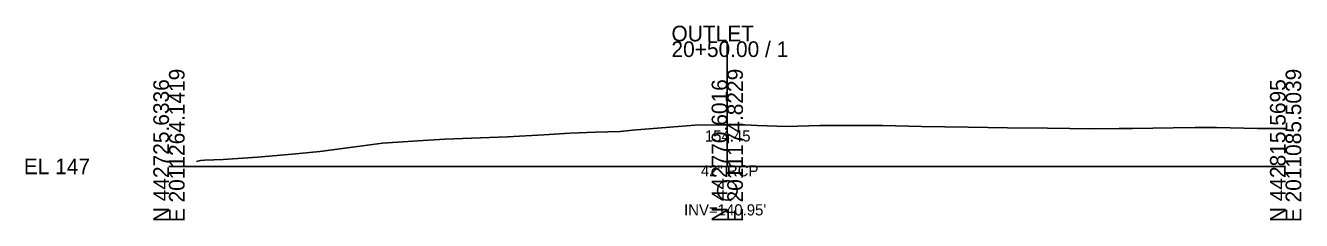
# Model space of a CAD drawing. Extents: x -26 to 1203, y -15 to 9526.
# Drawn here: x 974.3 to 1202.8, y 490.3 to 525.2 of the extents above; entities that cross this region are included whole.
import ezdxf

# ---------------------------------------------------------------- set-up
doc = ezdxf.new("R2010")
doc.units = 0
for name, color, linetype in [('Exist Cross Section Cell', 7, 'Continuous'), ('Exist XS Center Line Elevation Label', 7, 'Continuous'), ('Exist XS Ground Line', 7, 'Continuous'), ('Prop XSC Text', 7, 'Continuous')]:
    doc.layers.add(name, color=color, linetype=linetype)

msp = doc.modelspace()

# ---------------------------------------------------------------- linework, layer by layer
at = {"layer": 'Exist Cross Section Cell'}
for p, q in [((1100, 500), (1100, 522.39)), ((1000, 500), (1100, 500)), ((1100, 500), (1200, 500))]:
    msp.add_line(p, q, dxfattribs=at)
at = {"layer": 'Exist XS Ground Line'}
msp.add_lwpolyline([(1004.94, 500.9), (1005.66, 501.03), (1006.34, 501.11), (1009.71, 501.23), (1015.83, 501.65), (1022.04, 502.18), (1027.03, 502.69), (1031.95, 503.29), (1038.22, 504.15), (1044.59, 504.56), (1049.42, 504.88), (1054.19, 505.05), (1060.62, 505.26), (1067.14, 505.64), (1071.81, 505.96), (1076.42, 506.11), (1080.8, 506.25), (1083.01, 506.47), (1089.68, 507.04), (1094.2, 507.38), (1098.66, 507.46), (1100, 507.45), (1103.14, 507.41), (1105.4, 507.31), (1110.59, 507.16), (1116.6, 507.29), (1118.04, 507.3), (1120.9, 507.31), (1125.48, 507.32), (1127.79, 507.34), (1134.78, 507.14), (1138.99, 507.06), (1143.14, 507), (1150.18, 506.9), (1157.33, 506.82), (1161.38, 506.78), (1165.38, 506.75), (1170.16, 506.76), (1172.57, 506.78), (1179.87, 506.92), (1183.77, 506.98), (1187.61, 506.94), (1194.97, 506.76), (1200, 506.8)], dxfattribs=at)
at = {"layer": 'Prop XSC Text'}
msp.add_circle((1100, 495.7), 1.75, dxfattribs=at)

# ---------------------------------------------------------------- texts
at = {"layer": 'Exist Cross Section Cell'}
for s, p in [('OUTLET', (1090, 522.39)), ('20+50.00 / 1', (1090, 519.59)), ('EL 147', (974, 498.6))]:
    msp.add_text(s, height=2.8, dxfattribs=at).set_placement(p)
for s, p in [('E 2011264.1419', (1002.8, 490)), ('E 2011174.8229', (1102.8, 490)), ('E 2011085.5039', (1202.8, 490)), ('N 442725.6336', (1000, 490)), ('N 442770.6016', (1100, 490)), ('N 442815.5695', (1200, 490))]:
    msp.add_text(s, height=2.8, rotation=90, dxfattribs=at).set_placement(p)
at = {"layer": 'Exist XS Center Line Elevation Label'}
msp.add_text('154.45', height=2, dxfattribs=at).set_placement((1095.98, 504.45))
at = {"layer": 'Prop XSC Text'}
for s, p in [('42" RCP', (1095.26, 498.21)), ("INV=140.95'", (1092.26, 491.21))]:
    msp.add_text(s, height=2, dxfattribs=at).set_placement(p)

doc.saveas('drawing.dxf')
